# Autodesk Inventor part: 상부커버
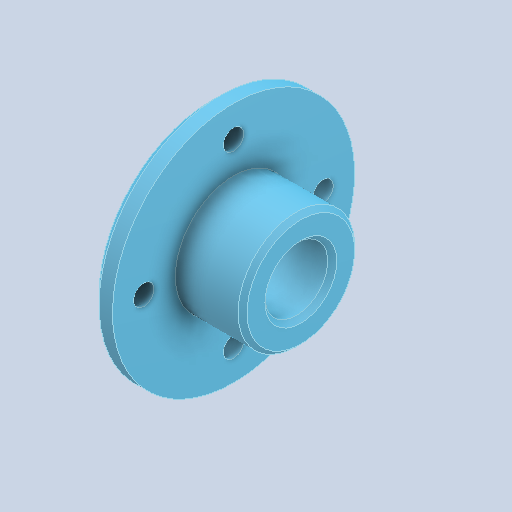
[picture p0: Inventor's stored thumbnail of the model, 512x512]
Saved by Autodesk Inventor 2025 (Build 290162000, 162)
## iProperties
Created: 2025-08
Part Number: 상부커버
Material: 알루미늄 6061
Document SubType Name: Modeling
Designer: infra028
Density: 2.71 g/cm^3
Appearance: 기본값
Author: jhkim
Sending System: Autodesk Inventor 2026
Preprocessor: ST-DEVELOPER v20.1
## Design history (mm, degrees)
feature "솔리드1"
node "솔리드2"
